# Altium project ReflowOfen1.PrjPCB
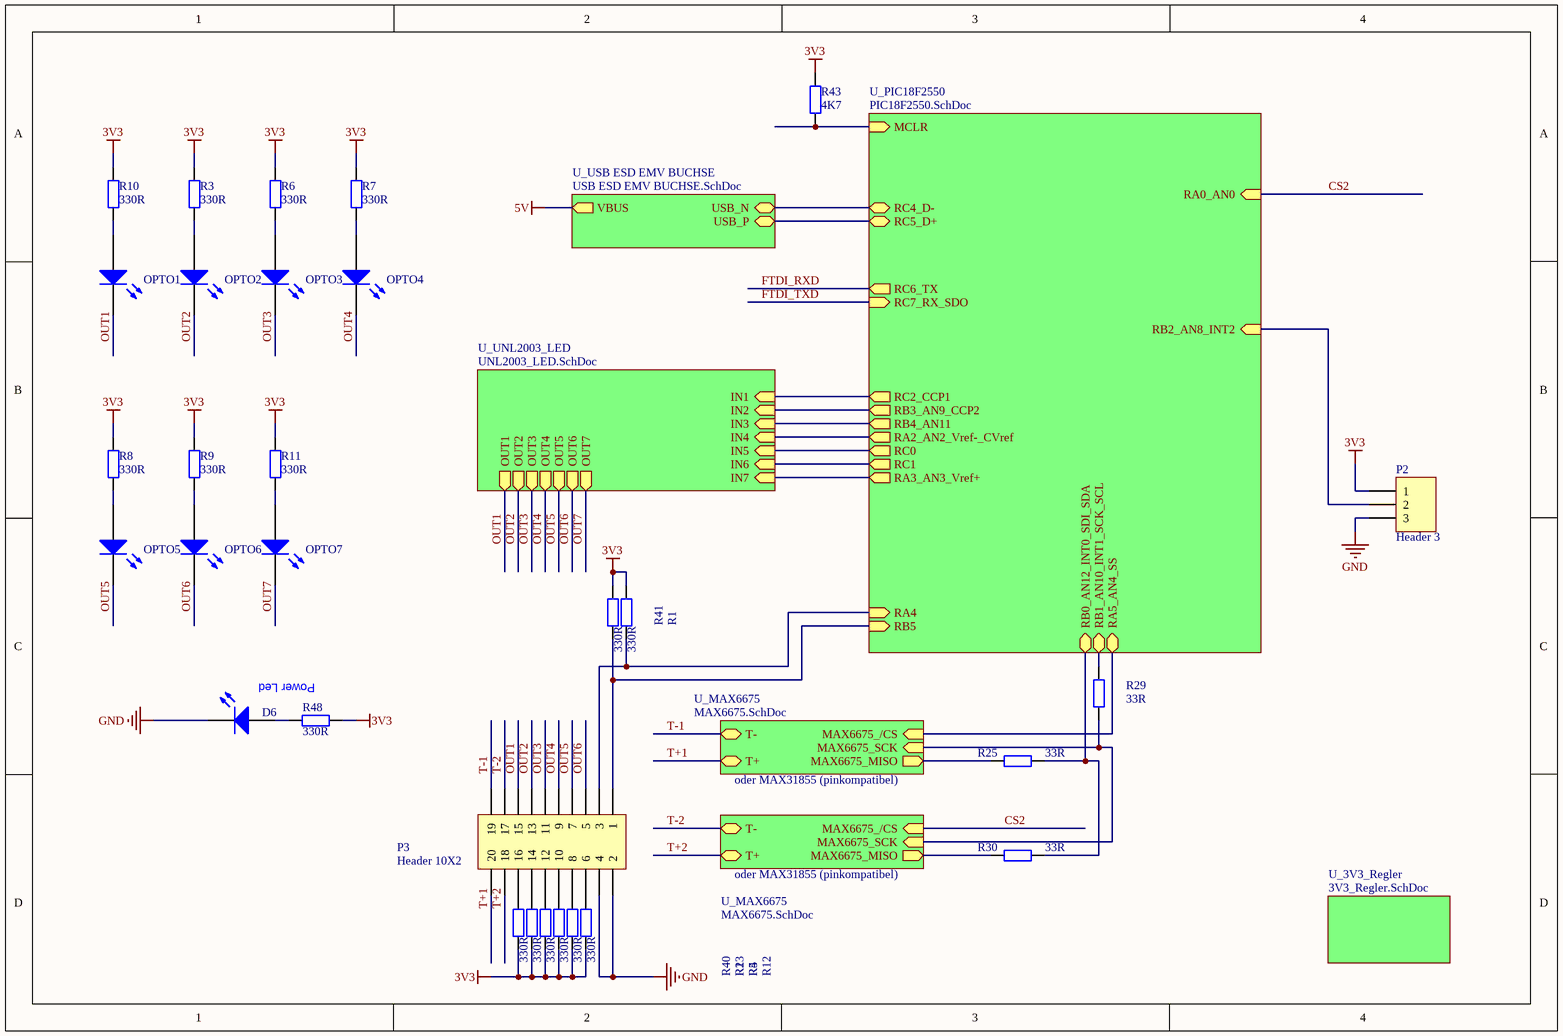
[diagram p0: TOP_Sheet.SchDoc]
6 sheets, 51 parts. Net scope: hierarchical (ports join the sheet entries above them; power ports are global).
Board file: Reflow_1.1.PcbDoc
Sheets:
  TOP_Sheet.SchDoc
    U_3V3_Regler = 3V3_Regler.SchDoc
    U_PIC18F2550 = PIC18F2550.SchDoc
    U_MAX6675 = MAX6675.SchDoc
    U_UNL2003_LED = UNL2003_LED.SchDoc
    U_USB ESD EMV BUCHSE = USB ESD EMV BUCHSE.SchDoc
    U_MAX6675 = MAX6675.SchDoc

## Sheet TOP_Sheet.SchDoc
size A4; DocumentNumber: 1; SheetNumber: 1; SheetTotal: 11; Abteilung: Hard/Software Entwicklung

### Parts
D6  LED1  [LED-1]  (value not drawn)
OPTO1  (no value)  [OPTO_0805_POL]
OPTO2  (no value)  [OPTO_0805_POL]
OPTO3  (no value)  [OPTO_0805_POL]
OPTO4  (no value)  [OPTO_0805_POL]
OPTO5  (no value)  [OPTO_0805_POL]
OPTO6  (no value)  [OPTO_0805_POL]
OPTO7  (no value)  [OPTO_0805_POL]
P2  Header 3  [HDR1X3]
P3  Header 10X2  [HDR2X10]
R1  330R  [RLCDT_1206]
R2  330R  [RLCDT_1206]
R3  330R  [RLCDT_1206]
R4  330R  [RLCDT_1206]
R5  330R  [RLCDT_1206]
R6  330R  [RLCDT_1206]
R7  330R  [RLCDT_1206]
R8  330R  [RLCDT_1206]
R9  330R  [RLCDT_1206]
R10  330R  [RLCDT_1206]
R11  330R  [RLCDT_1206]
R12  330R  [RLCDT_1206]
R13  330R  [RLCDT_1206]
R25  33R  [RLCDT_1206]
R29  33R  [RLCDT_1206]
R30  33R  [RLCDT_1206]
R40  330R  [RLCDT_1206]
R41  330R  [RLCDT_1206]
R43  4K7  [RLCDT_1206]
R48  330R  [RLCDT_1206]

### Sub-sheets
U_3V3_Regler = 3V3_Regler.SchDoc: no entries
U_MAX6675 = MAX6675.SchDoc: MAX6675_MISO (out), MAX6675_/CS (in), MAX6675_SCK (in), T+ (bidir), T- (bidir)
U_MAX6675 = MAX6675.SchDoc: MAX6675_MISO (out), MAX6675_/CS (in), MAX6675_SCK (in), T+ (bidir), T- (bidir)
U_PIC18F2550 = PIC18F2550.SchDoc: MCLR (in), RA0_AN0 (in), RA2_AN2_Vref-_CVref (out), RA3_AN3_Vref+ (out), RA4 (in), RA5_AN4_SS (bidir), RB0_AN12_INT0_SDI_SDA (bidir), RB1_AN10_INT1_SCK_SCL (bidir), RB2_AN8_INT2 (in), RB3_AN9_CCP2 (out), RB4_AN11 (out), RB5 (in), RC0 (out), RC1 (out), RC2_CCP1 (out), RC4_D- (bidir), RC5_D+ (bidir), RC6_TX (out), RC7_RX_SDO (in)
U_UNL2003_LED = UNL2003_LED.SchDoc: IN7 (in), IN6 (in), IN5 (in), IN4 (in), OUT1 (out), OUT2 (out), OUT3 (out), IN1 (in), IN2 (in), IN3 (in), OUT4 (out), OUT5 (out), OUT6 (out), OUT7 (out)
U_USB ESD EMV BUCHSE = USB ESD EMV BUCHSE.SchDoc: USB_N (bidir), USB_P (bidir), VBUS (out)

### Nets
3V3: P2.1 R1.2 R2.1 R3.2 R4.1 R5.1 R6.2 R7.2 R8.2 R9.2 R10.2 R11.2 R12.1 R13.1 R40.1 R41.2 R43.2 R48.2
GND: D6.2(K) P2.3 P3.2 P3.4
CS2: sheet U_PIC18F2550/RA0_AN0, sheet U_MAX6675/MAX6675_/CS
MCLR: R43.1 ; sheet U_PIC18F2550/MCLR
OUT1: OPTO1.K P3.15 ; sheet U_UNL2003_LED/OUT1
OUT2: OPTO2.K P3.13 ; sheet U_UNL2003_LED/OUT2
OUT3: OPTO3.K P3.11 ; sheet U_UNL2003_LED/OUT3
OUT4: OPTO4.K P3.9 ; sheet U_UNL2003_LED/OUT4
OUT5: OPTO5.K P3.7 ; sheet U_UNL2003_LED/OUT5
OUT6: OPTO6.K P3.5 ; sheet U_UNL2003_LED/OUT6
OUT7: OPTO7.K ; sheet U_UNL2003_LED/OUT7
T+1: P3.20 ; sheet U_MAX6675/T+
T+2: P3.18 ; sheet U_MAX6675/T+
T-1: P3.19 ; sheet U_MAX6675/T-
T-2: P3.17 ; sheet U_MAX6675/T-
USB_N: sheet U_PIC18F2550/RC4_D-, sheet U_USB ESD EMV BUCHSE/USB_N
USB_P: sheet U_PIC18F2550/RC5_D+, sheet U_USB ESD EMV BUCHSE/USB_P
NetD6_1: D6.1(A) R48.1
NetIC3A_5: R29.2 ; sheet U_MAX6675/MAX6675_SCK, sheet U_MAX6675/MAX6675_SCK
NetIC3A_6: sheet U_PIC18F2550/RA5_AN4_SS, sheet U_MAX6675/MAX6675_/CS
NetIC3A_7: R25.2 ; sheet U_MAX6675/MAX6675_MISO
NetIC3B_7: R30.2 ; sheet U_MAX6675/MAX6675_MISO
NetIC4_1: sheet U_PIC18F2550/RA3_AN3_Vref+, sheet U_UNL2003_LED/IN7
NetIC4_2: sheet U_PIC18F2550/RC1, sheet U_UNL2003_LED/IN6
NetIC4_3: sheet U_PIC18F2550/RC0, sheet U_UNL2003_LED/IN5
NetIC4_4: sheet U_PIC18F2550/RA2_AN2_Vref-_CVref, sheet U_UNL2003_LED/IN4
NetIC4_5: sheet U_PIC18F2550/RB4_AN11, sheet U_UNL2003_LED/IN3
NetIC4_6: sheet U_PIC18F2550/RB3_AN9_CCP2, sheet U_UNL2003_LED/IN2
NetIC4_7: sheet U_PIC18F2550/RC2_CCP1, sheet U_UNL2003_LED/IN1
NetOPTO1_A: OPTO1.A R10.1
NetOPTO2_A: OPTO2.A R3.1
NetOPTO3_A: OPTO3.A R6.1
NetOPTO4_A: OPTO4.A R7.1
NetOPTO5_A: OPTO5.A R8.1
NetOPTO6_A: OPTO6.A R9.1
NetOPTO7_A: OPTO7.A R11.1
NetP2_2: P2.2 ; sheet U_PIC18F2550/RB2_AN8_INT2
NetP3_1: P3.1 R41.1 ; sheet U_PIC18F2550/RB5
NetP3_3: P3.3 R1.1 ; sheet U_PIC18F2550/RA4
NetP3_6: P3.6 R5.2
NetP3_8: P3.8 R2.2
NetP3_10: P3.10 R40.2
NetP3_12: P3.12 R12.2
NetP3_14: P3.14 R4.2
NetP3_16: P3.16 R13.2
NetR25_1: R25.1 R30.1 ; sheet U_PIC18F2550/RB0_AN12_INT0_SDI_SDA
NetR29_1: R29.1 ; sheet U_PIC18F2550/RB1_AN10_INT1_SCK_SCL

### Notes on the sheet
- Power Led
- oder MAX31855 (pinkompatibel)

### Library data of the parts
D6 = LED1: Typical RED GaAs LED
OPTO1-OPTO7 = OPTO_LED_KP-2012MGC: LED, 0805, mega green
P2 = Header 3: Header, 3-Pin
P3 = Header 10X2: Header, 10-Pin, Dual row
R1-R13 R25 R29 R30 R40 R41 R43 R48 = R: Widerstand

## Sheet 3V3_Regler.SchDoc
size A4; DocumentNumber: 2; SheetNumber: 2; SheetTotal: 11; PageSetup: Record=PageOptions|CenterHorizontal=True|CenterVertical=True|PrintScale=0.70|XCorrection=1.00|YCorrection=1.00|PrintKind=0|BorderSize=5000000|LeftOffset=5|BottomOffset=0|Orientation=1|PaperLength=1000|PaperWidth=1000|Scale=100|PaperSource=7|PrintQuality=-4|MediaType=1|DitherType=10|PaperKind=A4|PrintScaleMode=1; Abteilung: Hard/Software Entwicklung
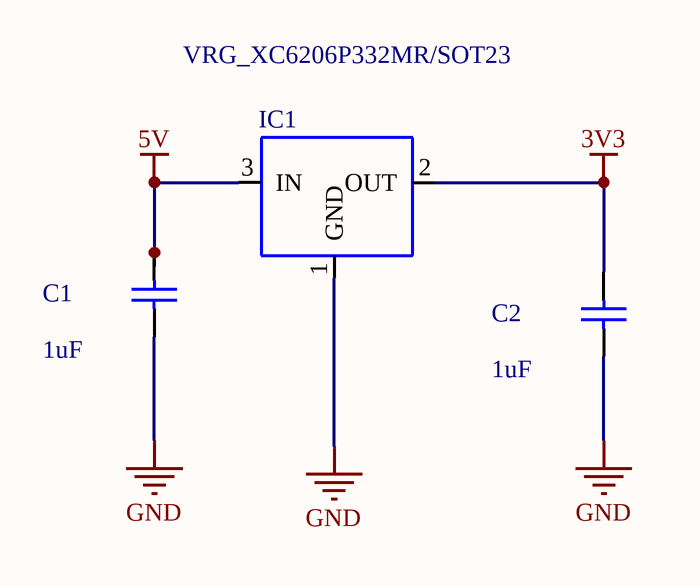
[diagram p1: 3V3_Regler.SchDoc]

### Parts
C1  1uF  [RLCDT_1206]
C2  1uF  [RLCDT_1206]
IC1  VRG_XC6206P332MR/SOT23  [RLCDT_SOT23]

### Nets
3V3: C2.1 IC1.2(OUT)
5V: C1.1 IC1.3(IN)
GND: C1.2 C2.2 IC1.1(GND)

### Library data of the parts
C1 C2 = C_KERAMIK: Kondensator, Keramik
IC1 = VRG_XC6206P332MR/SOT23: VOLTAGE REGULATOR 3V3 250mA; B_Bestellnummer: 58796980; D_Hersteller: TOREX

## Sheet PIC18F2550.SchDoc
size A4; DocumentNumber: 3; SheetNumber: 3; SheetTotal: 11; Abteilung: Hard/Software Entwicklung
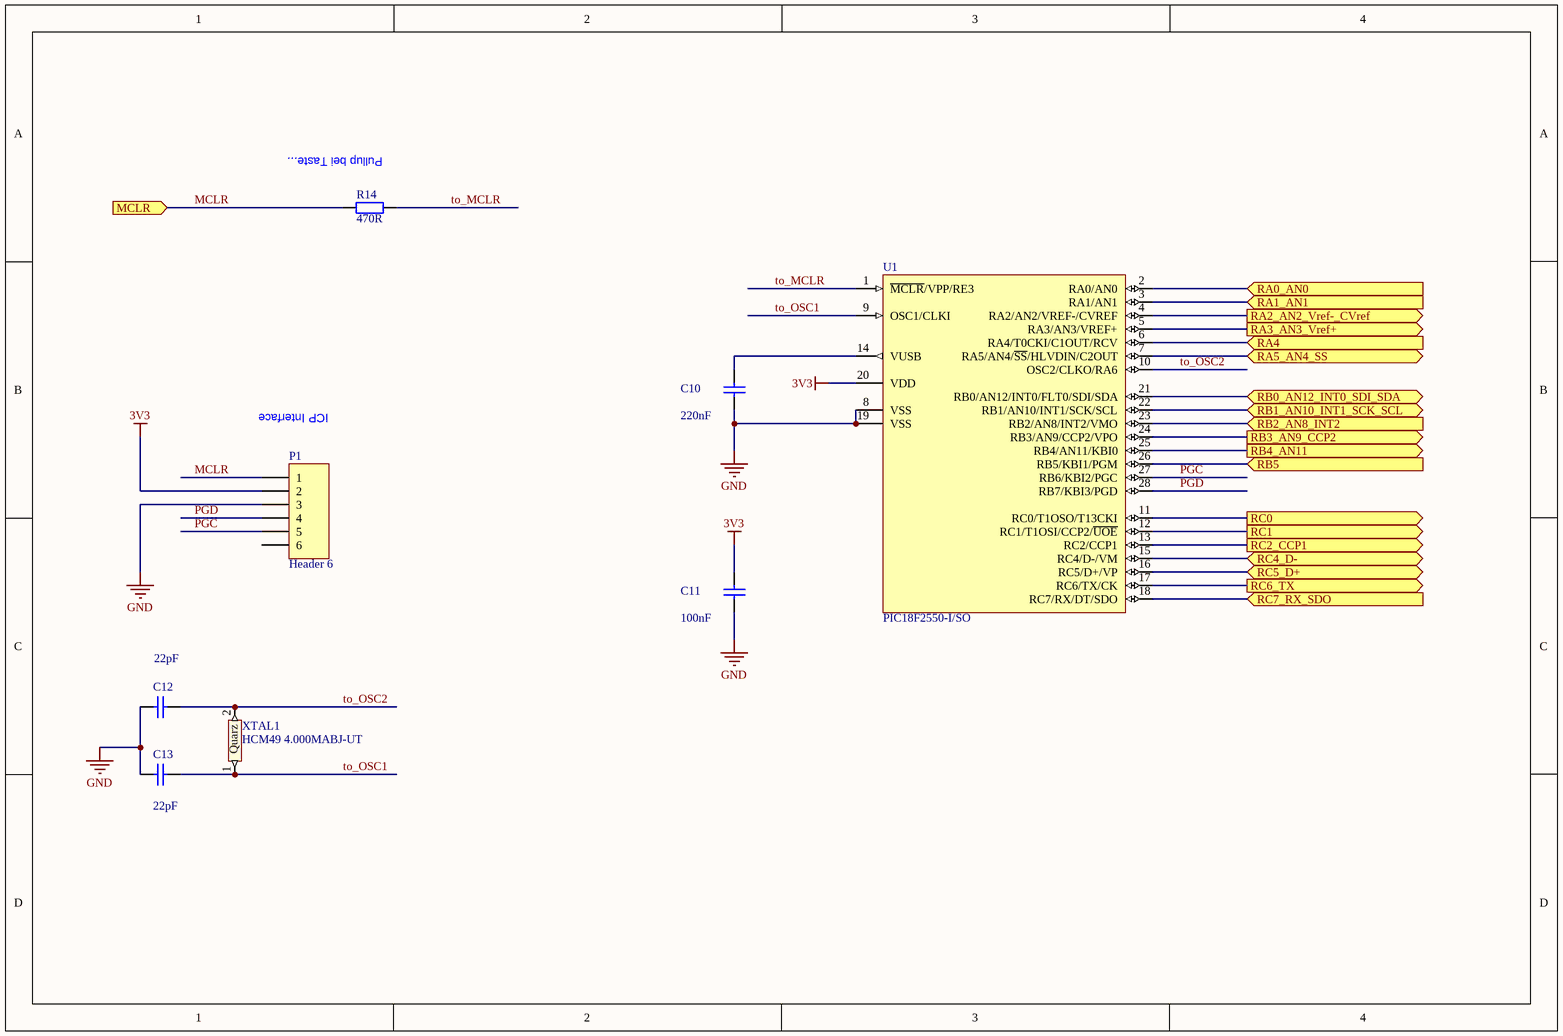
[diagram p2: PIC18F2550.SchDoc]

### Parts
C10  220nF  [RLCDT_1206]
C11  100nF  [RLCDT_1206]
C12  22pF  [RLCDT_1206]
C13  22pF  [RLCDT_1206]
P1  Header 6  [HDR1X6]
R14  470R  [RLCDT_1206]
U1  PIC18F2550-I/SO  [SOIC-SO28_N]
XTAL1  HCM49 4.000MABJ-UT  [IC_M-HCM49]

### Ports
MCLR (in), RA0_AN0 (in), RA1_AN1 (in), RA2_AN2_Vref-_CVref (out), RA3_AN3_Vref+ (out), RA4 (in), RA5_AN4_SS (bidir), RB0_AN12_INT0_SDI_SDA (bidir), RB1_AN10_INT1_SCK_SCL (bidir), RB2_AN8_INT2 (in), RB3_AN9_CCP2 (out), RB4_AN11 (out), RB5 (in), RC0 (out), RC1 (out), RC2_CCP1 (out), RC4_D- (bidir), RC5_D+ (bidir), RC6_TX (out), RC7_RX_SDO (in)

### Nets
3V3: C11.1 P1.2 U1.20(VDD)
GND: C10.2 C11.2 C12.1 C13.1 P1.3 U1.8(VSS) U1.19(VSS)
CS2: U1.2(RA0/AN0) ; port RA0_AN0
FTDI_RXD: U1.17(RC6/TX/CK) ; port RC6_TX
FTDI_TXD: U1.18(RC7/RX/DT/SDO) ; port RC7_RX_SDO
MCLR: P1.1 R14.2 ; port MCLR
PGC: P1.5 U1.27(RB6/KBI2/PGC)
PGD: P1.4 U1.28(RB7/KBI3/PGD)
to_MCLR: R14.1 U1.1(~{MCLR}/VPP/RE3)
to_OSC1: C13.2 U1.9(OSC1/CLKI) XTAL1.1
to_OSC2: C12.2 U1.10(OSC2/CLKO/RA6) XTAL1.2
USB_N: U1.15(RC4/D-/VM) ; port RC4_D-
USB_P: U1.16(RC5/D+/VP) ; port RC5_D+
NetC10_1: C10.1 U1.14(VUSB)
NetIC3A_6: U1.7(RA5/AN4/~{SS}/HLVDIN/C2OUT) ; port RA5_AN4_SS
NetIC4_1: U1.5(RA3/AN3/VREF+) ; port RA3_AN3_Vref+
NetIC4_2: U1.12(RC1/T1OSI/CCP2/~{UOE}) ; port RC1
NetIC4_3: U1.11(RC0/T1OSO/T13CKI) ; port RC0
NetIC4_4: U1.4(RA2/AN2/VREF-/CVREF) ; port RA2_AN2_Vref-_CVref
NetIC4_5: U1.25(RB4/AN11/KBI0) ; port RB4_AN11
NetIC4_6: U1.24(RB3/AN9/CCP2/VPO) ; port RB3_AN9_CCP2
NetIC4_7: U1.13(RC2/CCP1) ; port RC2_CCP1
NetP2_2: U1.23(RB2/AN8/INT2/VMO) ; port RB2_AN8_INT2
NetP3_1: U1.26(RB5/KBI1/PGM) ; port RB5
NetP3_3: U1.6(RA4/T0CKI/C1OUT/RCV) ; port RA4
NetR25_1: U1.21(RB0/AN12/INT0/FLT0/SDI/SDA) ; port RB0_AN12_INT0_SDI_SDA
NetR29_1: U1.22(RB1/AN10/INT1/SCK/SCL) ; port RB1_AN10_INT1_SCK_SCL
NetU1_3: U1.3(RA1/AN1) ; port RA1_AN1

Not connected (* = marked no-connect by the designer): P1 6

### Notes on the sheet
- (near R14) Pullup bei Taste...
- ICP Interface

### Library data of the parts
C10-C13 = C_KERAMIK: Kondensator, Keramik
P1 = Header 6: Header, 6-Pin
R14 = R: Widerstand
U1 = PIC18F2550-I/SO: High Performance, Enhanced Flash, USB Microcontroller with nanoWatt Technology, 32K Flash, 28-Pin SOIC, Industrial Temperature Range
XTAL1 = IC_XTAL_4MHz: Quarz 4MHz; B_Bestellnummer: 1611739; D_Hersteller: CITIZEN AMERICA

## Sheet MAX6675.SchDoc
size A4; DocumentNumber: 6; SheetNumber: 6; SheetTotal: 11; Abteilung: Hard/Software Entwicklung
Used 2 times, as channels U_MAX6675, U_MAX6675. Parts and nets are listed once, with the designators drawn on the sheet.
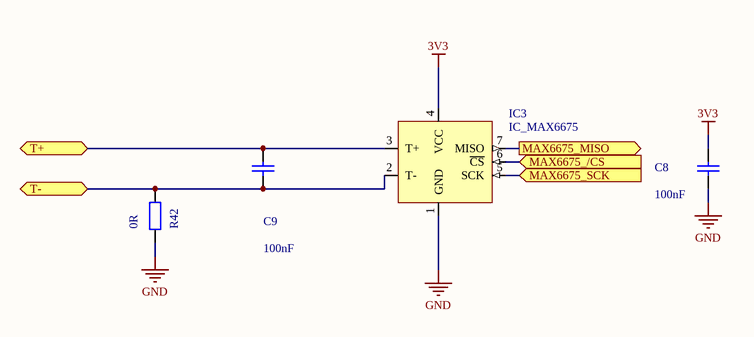
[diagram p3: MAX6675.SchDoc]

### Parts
C8  100nF  [RLCDT_1206]
C9  100nF  [RLCDT_1206]
IC3  IC_MAX6675  [IC_SOIC150_8]
R42  0R  [RLCDT_1206]

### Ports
MAX6675_/CS (in), MAX6675_MISO (out), MAX6675_SCK (in), T+ (bidir), T- (bidir)

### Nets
3V3: C8.1 IC3.4(VCC)
GND: C8.2 IC3.1(GND) R42.1
MAX6675_/CS: IC3.6(~{CS}) ; port MAX6675_/CS
MAX6675_MISO: IC3.7(MISO) ; port MAX6675_MISO
MAX6675_SCK: IC3.5(SCK) ; port MAX6675_SCK
T+: C9.1 IC3.3(T+) ; port T+
T-: C9.2 IC3.2(T-) R42.2 ; port T-

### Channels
U_MAX6675: designators end in A; ports MAX6675_/CS=NetIC3A_6 MAX6675_MISO=NetIC3A_7 MAX6675_SCK=NetIC3A_5 T+=T+1 T-=T-1
U_MAX6675: designators end in B; ports MAX6675_/CS=CS2 MAX6675_MISO=NetIC3B_7 MAX6675_SCK=NetIC3A_5 T+=T+2 T-=T-2

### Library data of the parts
C8 C9 = C_KERAMIK: Kondensator, Keramik
R42 = R: Widerstand

## Sheet UNL2003_LED.SchDoc
size A4; DocumentNumber: 8; SheetNumber: 8; SheetTotal: 11; Abteilung: Hard/Software Entwicklung
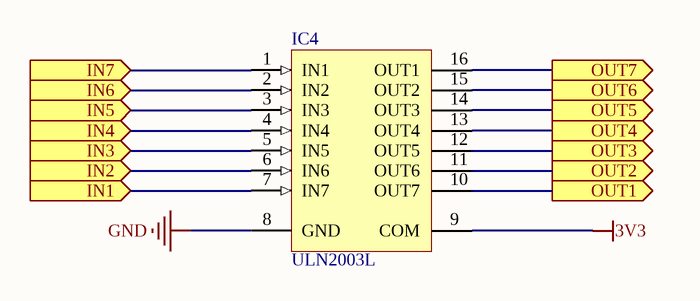
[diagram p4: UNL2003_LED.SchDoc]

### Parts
IC4  ULN2003L  [L16_N]

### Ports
IN1 (in), IN2 (in), IN3 (in), IN4 (in), IN5 (in), IN6 (in), IN7 (in), OUT1 (out), OUT2 (out), OUT3 (out), OUT4 (out), OUT5 (out), OUT6 (out), OUT7 (out)

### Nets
3V3: IC4.9(COM)
GND: IC4.8(GND)
OUT1: IC4.10(OUT7) ; port OUT1
OUT2: IC4.11(OUT6) ; port OUT2
OUT3: IC4.12(OUT5) ; port OUT3
OUT4: IC4.13(OUT4) ; port OUT4
OUT5: IC4.14(OUT3) ; port OUT5
OUT6: IC4.15(OUT2) ; port OUT6
OUT7: IC4.16(OUT1) ; port OUT7
NetIC4_1: IC4.1(IN1) ; port IN7
NetIC4_2: IC4.2(IN2) ; port IN6
NetIC4_3: IC4.3(IN3) ; port IN5
NetIC4_4: IC4.4(IN4) ; port IN4
NetIC4_5: IC4.5(IN5) ; port IN3
NetIC4_6: IC4.6(IN6) ; port IN2
NetIC4_7: IC4.7(IN7) ; port IN1

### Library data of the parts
IC4 = ULN2003L: High-Voltage, High-Current Darlington Array

## Sheet USB ESD EMV BUCHSE.SchDoc
size A3; Date: 24.10.2012; CheckedBy: MRipel; Author: Burmeister; Organization: RUETZ TECHNOLOGIES; Address1: Walter-Gropius-Str. 17; Address2: 80807; Address3: München; Address4: Germany; DocumentNumber: 4; Revision: 1.0; SheetNumber: 4; SheetTotal: 11; Abteilung: Hard/Software Entwicklung; Sachnummer: DCB-25863; Datum_V1: 24.10.2012; Version_V1: 1.0; Ersteller_V1: Burmeister; Geprueft_V1: MRipel
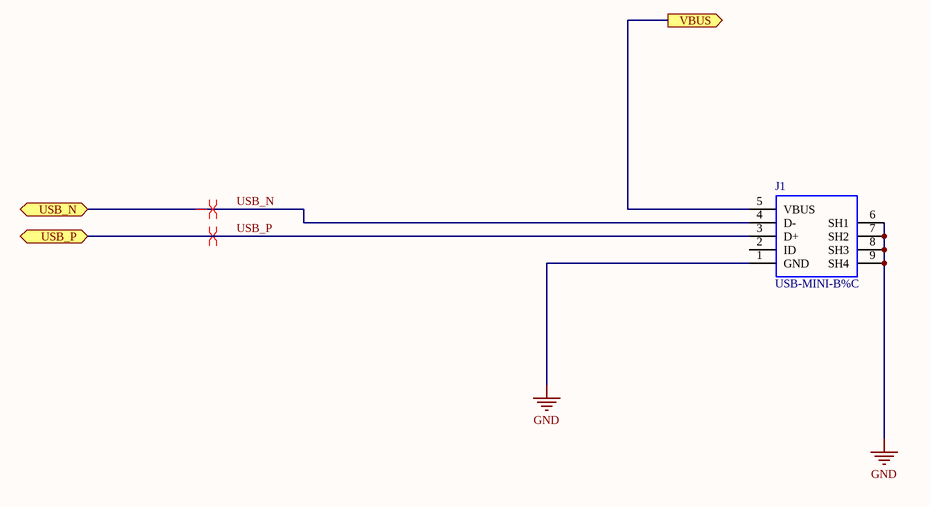
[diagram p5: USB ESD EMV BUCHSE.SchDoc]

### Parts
J1  USB-MINI-B%C  [USB-MINI-B_2]

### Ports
USB_N (bidir), USB_P (bidir), VBUS (out)

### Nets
5V: J1.5(VBUS) ; port VBUS
GND: J1.1(GND) J1.6(SH1) J1.7(SH2) J1.8(SH3) J1.9(SH4)
USB_N: J1.4(D-) ; port USB_N
USB_P: J1.3(D+) ; port USB_P

Not connected (* = marked no-connect by the designer): J1 2(ID)

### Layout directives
differential pair: USB_N, USB_P

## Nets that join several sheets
3V3: TOP_Sheet (18 pins), 3V3_Regler (C2.1 IC1.2), PIC18F2550 (C11.1 P1.2 U1.20), U_MAX6675 (C8A.1 IC3A.4), UNL2003_LED (IC4.9), U_MAX6675 (C8B.1 IC3B.4)
5V: 3V3_Regler (C1.1 IC1.3), USB ESD EMV BUCHSE (J1.5)
GND: TOP_Sheet (D6.2 P2.3 P3.2 P3.4), 3V3_Regler (C1.2 C2.2 IC1.1), PIC18F2550 (7 pins), U_MAX6675 (C8A.2 IC3A.1 R42A.1), UNL2003_LED (IC4.8), USB ESD EMV BUCHSE (5 pins), U_MAX6675 (C8B.2 IC3B.1 R42B.1)
CS2: PIC18F2550 (U1.2), U_MAX6675 (IC3B.6)
MCLR: TOP_Sheet (R43.1), PIC18F2550 (P1.1 R14.2)
NetIC3A_5: TOP_Sheet (R29.2), U_MAX6675 (IC3A.5), U_MAX6675 (IC3B.5)
NetIC3A_6: PIC18F2550 (U1.7), U_MAX6675 (IC3A.6)
NetIC3A_7: TOP_Sheet (R25.2), U_MAX6675 (IC3A.7)
NetIC3B_7: TOP_Sheet (R30.2), U_MAX6675 (IC3B.7)
NetIC4_1: PIC18F2550 (U1.5), UNL2003_LED (IC4.1)
NetIC4_2: PIC18F2550 (U1.12), UNL2003_LED (IC4.2)
NetIC4_3: PIC18F2550 (U1.11), UNL2003_LED (IC4.3)
NetIC4_4: PIC18F2550 (U1.4), UNL2003_LED (IC4.4)
NetIC4_5: PIC18F2550 (U1.25), UNL2003_LED (IC4.5)
NetIC4_6: PIC18F2550 (U1.24), UNL2003_LED (IC4.6)
NetIC4_7: PIC18F2550 (U1.13), UNL2003_LED (IC4.7)
NetP2_2: TOP_Sheet (P2.2), PIC18F2550 (U1.23)
NetP3_1: TOP_Sheet (P3.1 R41.1), PIC18F2550 (U1.26)
NetP3_3: TOP_Sheet (P3.3 R1.1), PIC18F2550 (U1.6)
NetR25_1: TOP_Sheet (R25.1 R30.1), PIC18F2550 (U1.21)
NetR29_1: TOP_Sheet (R29.1), PIC18F2550 (U1.22)
OUT1: TOP_Sheet (OPTO1.K P3.15), UNL2003_LED (IC4.10)
OUT2: TOP_Sheet (OPTO2.K P3.13), UNL2003_LED (IC4.11)
OUT3: TOP_Sheet (OPTO3.K P3.11), UNL2003_LED (IC4.12)
OUT4: TOP_Sheet (OPTO4.K P3.9), UNL2003_LED (IC4.13)
OUT5: TOP_Sheet (OPTO5.K P3.7), UNL2003_LED (IC4.14)
OUT6: TOP_Sheet (OPTO6.K P3.5), UNL2003_LED (IC4.15)
OUT7: TOP_Sheet (OPTO7.K), UNL2003_LED (IC4.16)
T+1: TOP_Sheet (P3.20), U_MAX6675 (C9A.1 IC3A.3)
T+2: TOP_Sheet (P3.18), U_MAX6675 (C9B.1 IC3B.3)
T-1: TOP_Sheet (P3.19), U_MAX6675 (C9A.2 IC3A.2 R42A.2)
T-2: TOP_Sheet (P3.17), U_MAX6675 (C9B.2 IC3B.2 R42B.2)
USB_N: PIC18F2550 (U1.15), USB ESD EMV BUCHSE (J1.4)
USB_P: PIC18F2550 (U1.16), USB ESD EMV BUCHSE (J1.3)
